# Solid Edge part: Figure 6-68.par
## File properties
Author: Ashutosh-CADCIM
Template: Iso Metric Part.par
Last saved by: Ashutosh-CADCIM
Revision: 1
Application: Solid Edge
Accuracy: 0.990
Username: Ashutosh-CADCIM
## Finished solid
Body 1: solid body, 9 faces, 17 edges, 8 vertices.
  Faces by surface: plane 5, cylinder 4
  Edges by curve: circle 9, line 8
Bounding box of the edges (mm): 952.370 x 952.370 x 121.928, from (-476.1847, -476.1847, -121.9277) to (476.1847, 476.1847, 0).
Cylindrical faces by radius (mm): R36.4286 x1, R87.9372 x1, R320 x1, R476.1847 x1
Planar faces by outward normal: +z 2, -z 1, oblique 2
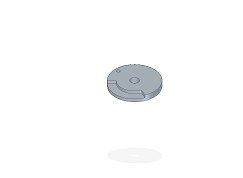
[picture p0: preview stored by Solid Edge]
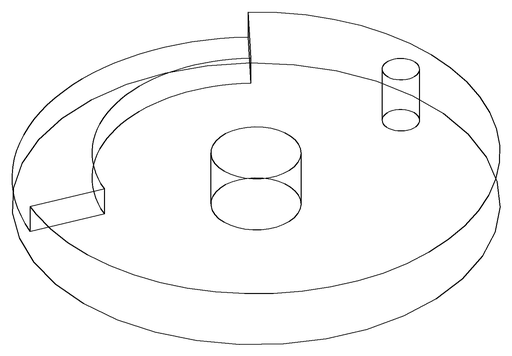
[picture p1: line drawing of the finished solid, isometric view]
